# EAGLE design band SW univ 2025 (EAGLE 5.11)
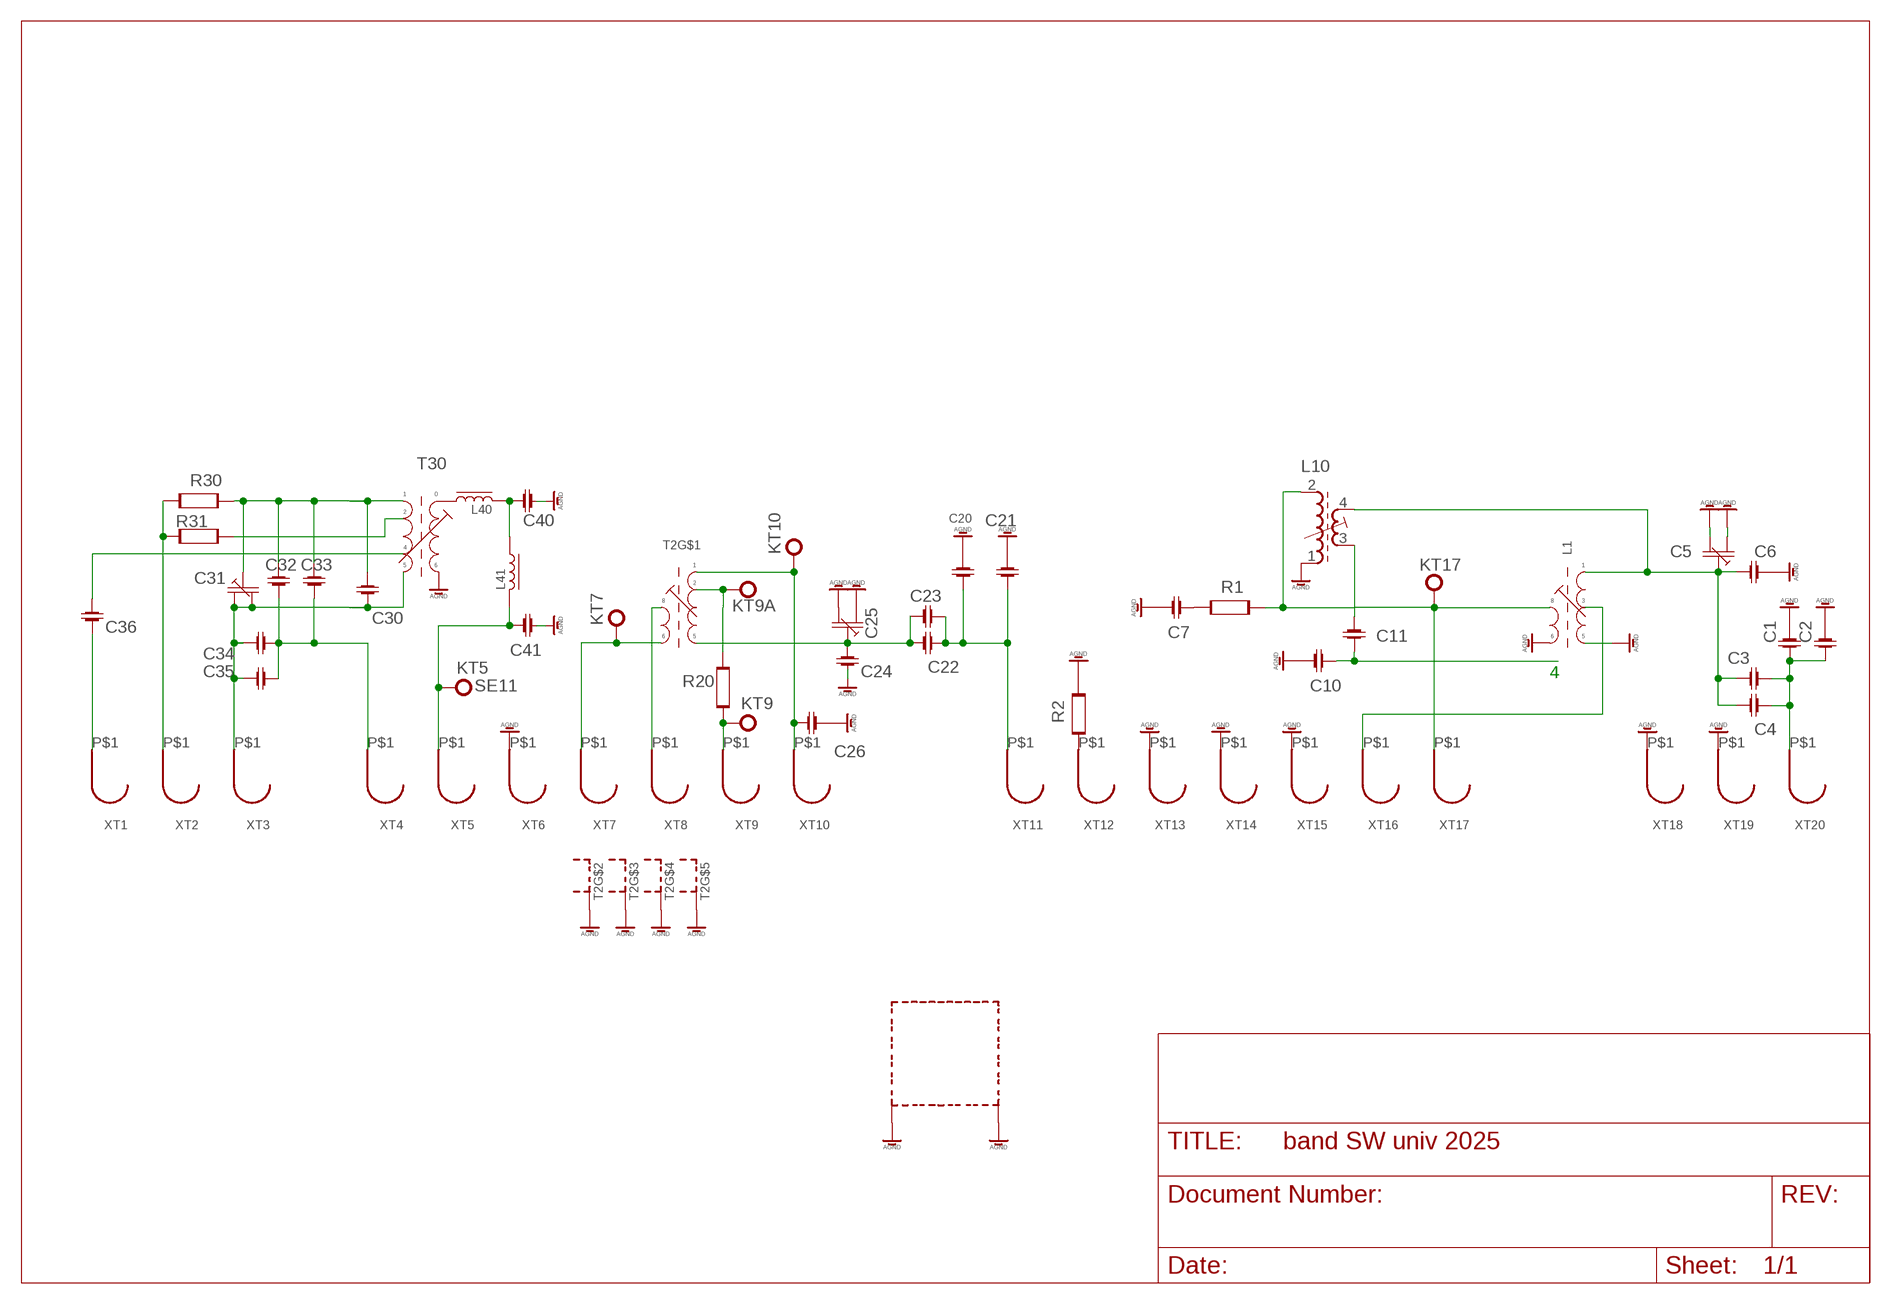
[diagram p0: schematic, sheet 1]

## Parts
C1  C-1206-0805  [RC-SMD-UNIV]
C2  C-1206-0805  [RC-SMD-UNIV]
C3  C-1206-0805  [RC-SMD-UNIV]
C4  C-1206-0805  [RC-SMD-UNIV]
C5  C-TRIM-AM  [C-TRIM-ORIG]
C6  C-1206-0805  [RC-SMD-UNIV]
C7  C-1206-0805  [RC-SMD-UNIV]
C10  C-1206-0805  [RC-SMD-UNIV]
C11  C-1206-0805  [RC-SMD-UNIV]
C20  C-1206-0805  [RC-SMD-UNIV]
C21  C-1206-0805  [RC-SMD-UNIV]
C22  C-1206-0805  [RC-SMD-UNIV]
C23  C-1206-0805  [RC-SMD-UNIV]
C24  C-1206-0805  [RC-SMD-UNIV]
C25  C-TRIM-AM  [C-TRIM-ORIG]
C26  C-1206-0805  [RC-SMD-UNIV]
C30  C-1206-0805  [RC-SMD-UNIV]
C31  C-TRIM-AM  [C-TRIM-ORIG]
C32  C-1206-0805  [RC-SMD-UNIV]
C33  C-1206-0805  [RC-SMD-UNIV]
C34  C-1206-0805  [RC-SMD-UNIV]
C35  C-1206-0805  [RC-SMD-UNIV]
C36  C-1206-0805  [RC-SMD-UNIV]
C40  C-1206-0805  [RC-SMD-UNIV]
C41  C-1206-0805  [RC-SMD-UNIV]
KT5  SE11  [SE11]
KT7  SE11  [SE11]
KT9  SE11  [SE11]
KT9A  SE11  [SE11]
KT10  SE11  [SE11]
KT17  SE11  [SE11]
L1  L-MOD-SW-IN-OPEN  [L-KW-LARGE]
L10  71-4-2143  [71-5]
L40  L-US0207/10  [0207/10]
L41  L-US0207/10  [0207/10]
R1  R-1206-0805  [RC-SMD-UNIV]
R2  R-1206-0805  [RC-SMD-UNIV]
R20  R-1206-0805  [RC-SMD-UNIV]
R30  R-1206-0805  [RC-SMD-UNIV]
R31  R-1206-0805  [RC-SMD-UNIV]
T2  L-MOD-SW-MIX-SHIELD  [L-10-7-MM]
T30  L-MOD-OSC-SW  [L-KW-LARGE]
XT1  CONTACT-RF  [CONTACT-RF]
XT2  CONTACT-RF  [CONTACT-RF]
XT3  CONTACT-RF  [CONTACT-RF]
XT4  CONTACT-RF  [CONTACT-RF]
XT5  CONTACT-RF  [CONTACT-RF]
XT6  CONTACT-RF  [CONTACT-RF]
XT7  CONTACT-RF  [CONTACT-RF]
XT8  CONTACT-RF  [CONTACT-RF]
XT9  CONTACT-RF  [CONTACT-RF]
XT10  CONTACT-RF  [CONTACT-RF]
XT11  CONTACT-RF  [CONTACT-RF]
XT12  CONTACT-RF  [CONTACT-RF]
XT13  CONTACT-RF  [CONTACT-RF]
XT14  CONTACT-RF  [CONTACT-RF]
XT15  CONTACT-RF  [CONTACT-RF]
XT16  CONTACT-RF  [CONTACT-RF]
XT17  CONTACT-RF  [CONTACT-RF]
XT18  CONTACT-RF  [CONTACT-RF]
XT19  CONTACT-RF  [CONTACT-RF]
XT20  CONTACT-RF  [CONTACT-RF]

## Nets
AGND: C1.P$2 C2.P$2 C5.P$6 C5.P$7 C6.P$2 C7.P$1 C10.P$1 C20.P$2 C21.P$2 C24.P$1 C25.P$6 C25.P$7 C26.P$1 C40.P$1 C41.P$2 L1.P$1 L1.P$2 L10.1(E1) L10.S1 L10.S2 R2.P$2 T2.11(S) T2.12(S) T2.13(S) T2.14(S) T30.P$2 XT6.P$1 XT13.P$1 XT14.P$1 XT15.P$1 XT18.P$1 XT19.P$1
KT17: KT17.MP L1.P$6 L10.2(A1) R1.P$2 XT17.P$1
N$1: C1.P$1 C2.P$1 C3.P$2 C4.P$2 XT20.P$1
N$2: C3.P$1 C4.P$1 C5.P$5 C6.P$1 L1.P$3 L10.4(A2)
N$3: KT7.MP T2.4 XT7.P$1
N$4: C7.P$2 R1.P$1
N$5: T2.5 XT8.P$1
N$6: KT9.MP R20.P$1 XT9.P$1
N$7: R30.P$2 R31.P$1 XT2.P$1
N$8: L1.P$5 XT16.P$1
N$9: C26.P$2 KT10.MP T2.1 XT10.P$1
N$10: R2.P$1 XT12.P$1
N$11: R31.P$2 T30.P$1
N$12: C22.P$2 C23.P$2 C24.P$2 C25.P$5 T2.3
N$13: C20.P$1 C21.P$1 C22.P$1 C23.P$1 XT11.P$1
N$14: C11.P$2 L10.3(E2)
N$15: C10.P$2 C11.P$1
N$18: L40.1 T30.P$3
N$19: C30.P$1 C31.P$5 C32.P$1 C33.P$1 R30.P$1 T30.P$5
N$20: C30.P$2 C31.P$6 C31.P$7 C34.P$2 C35.P$2 T30.P$6 XT3.P$1
N$21: C32.P$2 C33.P$2 C34.P$1 C35.P$1 XT4.P$1
N$23: C41.P$1 KT5.MP L41.2 XT5.P$1
N$24: C36.P$1 T30.P$4
N$25: C40.P$2 L40.2 L41.1
N$26: C36.P$2 XT1.P$1
N$31: KT9A.MP R20.P$2 T2.2

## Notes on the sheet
- 4

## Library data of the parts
C1-C4 C6 C7 C10 C11 C20-C24 C26 C30 C32-C36 C40 C41 = OKEAH:C-1206-0805
C5 C25 C31 = OKEAH:C-TRIM-AM
KT5 KT7 KT9 KT9A KT10 KT17 = solpad:SE11: SOLDER PAD
L1 = OKEAH:L-MOD-SW-IN-OPEN
L10 = L NEOSID:71-4-: TRANSFORMER adjustable filter transformer; OC_FARNELL: unknown; OC_NEWARK: unknown
L40 L41 = rcl:L-US: INDUCTOR, American symbol
R1 R2 R20 R30 R31 = OKEAH:R-1206-0805
T2 = OKEAH:L-MOD-SW-MIX-SHIELD
T30 = OKEAH:L-MOD-OSC-SW
XT1-XT20 = OKEAH:CONTACT-RF

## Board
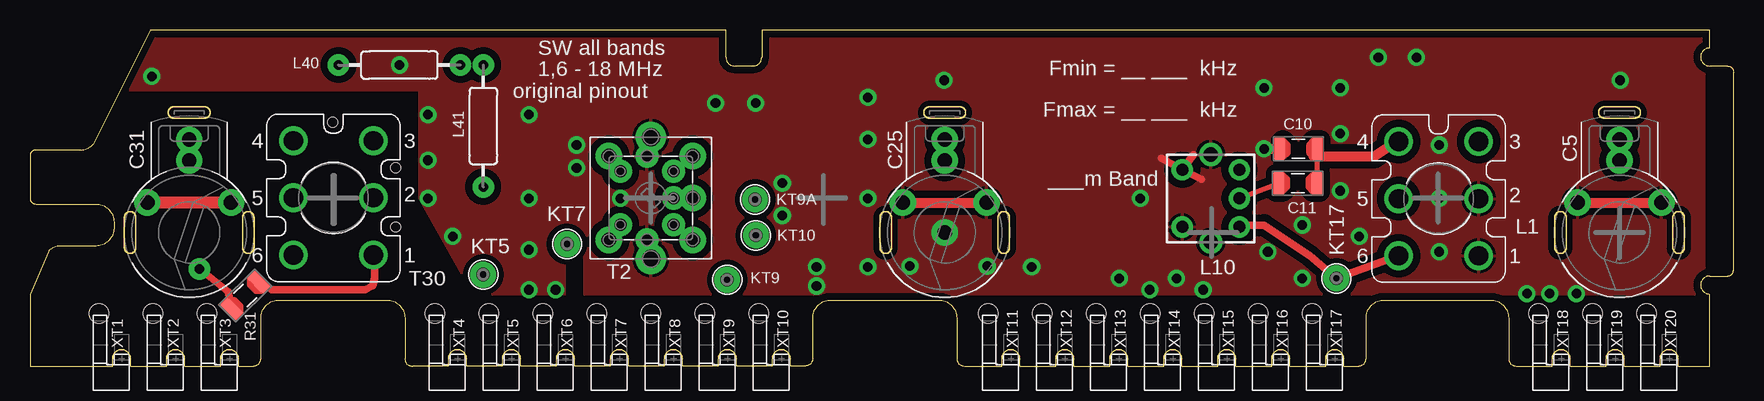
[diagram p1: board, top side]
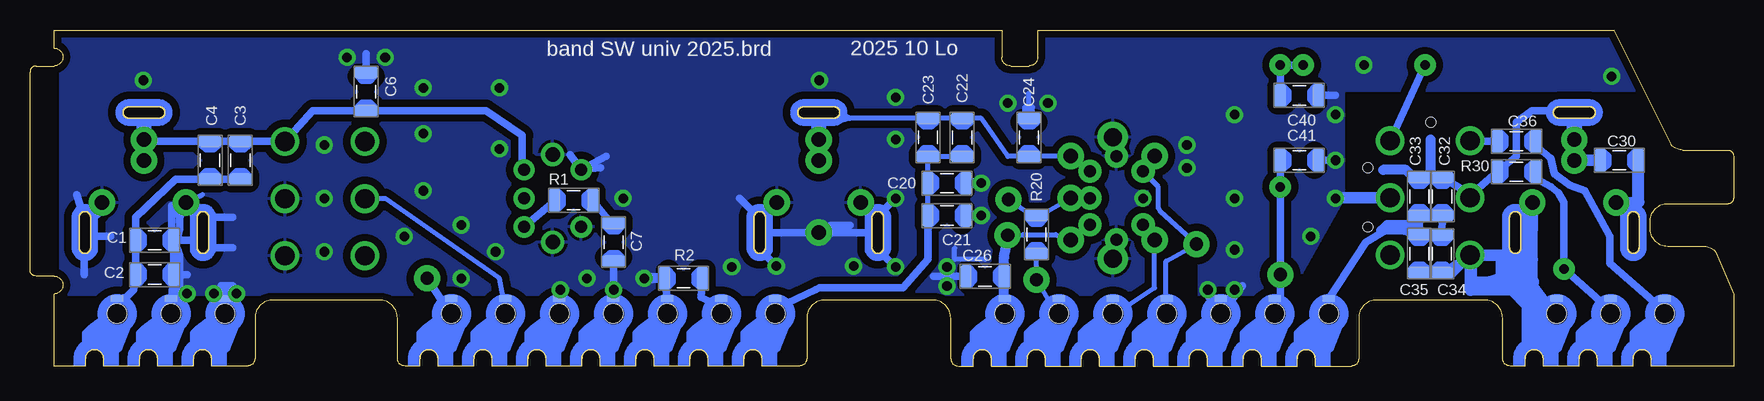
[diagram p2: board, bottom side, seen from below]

Size 142 x 28 mm. Coordinates in mm from the lower left corner, seen from the top.
Outline: 139 segments
Copper layers (1*16): Top 0.035mm / dielectric 1.5mm / Bottom 0.035mm
Design rules "default *": minimum track width 10mil, minimum drill 24mil, track to track 8mil, track to pad 8mil, pad to pad 8mil, via to via 8mil, smd to smd 8mil, copper to edge 8mil, drill to drill 8mil, minimum pad ring 10mil, minimum via ring 8mil, stop-mask expansion 4mil, vias tented up to drill 0mil, thermal gap 10mil
Holes 0.8 mm at 30.48,16.51 30.48,11.59 25.24,20.32
tRestrict: 1 lines
bRestrict: 2 lines

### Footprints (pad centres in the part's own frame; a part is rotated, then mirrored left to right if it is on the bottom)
RC-SMD-UNIV = smd 0.965 x 1.93: P$1 -1.587,0; P$2 1.587,0
C-TRIM-ORIG = drill 1.2 pad 2.184 round: P$4 7.739,0; P$5 5.992,0; P$6 2.5,3.493; P$7 2.5,-3.493
SE11 = drill 1.1 pad 2.159 round: MP 0,0
L-KW-LARGE = drill 1.6 round: P$1 0,0; P$2 0,4.763; P$3 0,9.525; P$4 -6.668,9.525; P$5 -6.668,4.763; P$6 -6.668,0
71-5 = drill 1 pad 1.778 round: 1 2.381,-2.381; 2 2.381,2.381; 3 0,2.381; 4 -2.381,2.381; 5 -2.381,-2.381 | drill 1.2 pad 1.93 round: S1 -3.651,0; S2 3.651,0
0207/10 = drill 0.8 pad 1.778 round: 1 -5.08,0; 2 5.08,0
L-10-7-MM = drill 1 pad 1.93 round: 1 -2.223,-1.905; 2 0,-1.905; 3 2.223,-1.905; 4 2.223,2.54; 5 -2.223,2.54; 12 -3.493,0.318; 13 3.493,0.318 | drill 1.2 pad 2.184 round: 6 -3.493,-3.493; 7 0,-3.493; 8 3.493,-3.493; 9 3.493,3.493; 10 -3.493,3.493 | drill 1.5 pad 2.54 round: 11 -5.08,0; 14 5.08,0
CONTACT-RF = smd 1.016 x 0.508 bottom: P$1 1,-5.625 | hole 1.6: 1,-4.375

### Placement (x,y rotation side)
C1  131.6,10.48 0 bottom
C2  131.6,7.62 0 bottom
C3  124.46,17.15 270 bottom
C4  127,17.15 270 bottom
C5  132.5,11.13 90 top
C6  113.98,22.86 90 bottom
C7  93.34,10.32 90 bottom
C10  105.73,18.1 0 top
C11  105.68,15.24 180 top
C20  65.56,15.24 0 bottom
C21  65.56,12.54 0 bottom
C22  64.29,19.05 90 bottom
C23  67.15,19.05 90 bottom
C24  58.74,19.05 270 bottom
C25  76.25,11.13 90 top
C26  62.39,7.46 0 bottom
C30  9.53,17.15 0 bottom
C31  13.27,11.13 90 top
C32  24.29,14.13 270 bottom
C33  26.19,14.13 270 bottom
C34  24.32,9.36 270 bottom
C35  26.19,9.37 270 bottom
C36  18.1,18.73 0 bottom
C40  36.2,22.54 180 bottom
C41  36.2,17.15 0 bottom
KT5  37.78,7.62 0 top
KT7  44.77,10.16 0 top
KT9  58.12,7.19 0 top
KT9A  60.44,13.88 0 top
KT10  60.51,10.89 0 top
KT17  108.9,7.3 0 top
L1  120.75,9.19 0 top
L10  98.42,13.97 270 top
L40  30.8,25.08 0 top
L41  37.78,20 270 top
R1  96.68,13.81 180 bottom
R2  87.52,7.3 180 bottom
R20  58.1,10.96 90 bottom
R30  18.1,16.19 0 bottom
R31  17.94,5.88 45 top
T2  51.75,14 90 top
T30  28.62,9.25 0 top
XT1  6.75,0 180 top
XT2  11.25,0 180 top
XT3  15.75,0 180 top
XT4  34.75,0 180 top
XT5  39.25,0 180 top
XT6  43.75,0 180 top
XT7  48.25,0 180 top
XT8  52.75,0 180 top
XT9  57.25,0 180 top
XT10  61.75,0 180 top
XT11  80.88,0 180 top
XT12  85.38,0 180 top
XT13  89.88,0 180 top
XT14  94.38,0 180 top
XT15  98.88,0 180 top
XT16  103.38,0 180 top
XT17  107.88,0 180 top
XT18  126.75,0 180 top
XT19  131.25,0 180 top
XT20  135.75,0 180 top

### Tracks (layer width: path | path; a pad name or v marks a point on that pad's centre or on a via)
AGND  (via drill 0.8 pad 1.42, 1.2 pad 2.18)
  Top 0.61: C5.P$6 C5.P$7 | 96.04,16.35 94.3,17.31 | 96.04,16.35 97.63,15.56 | 96.04,16.35 97,17.62
  Top 0.813: 102.55,18.1 C10.P$1
  Bottom 0.406: 127.64,14.29 128.27,13.97 C5.P$6 | 129.54,12.07 128.91,13.65 | C24.P$1 | C24.P$1 58.42,20.8 58.42,21.59 59.05,21.59 59.05,20.8 C24.P$1 | C24.P$1 58.74,22.7 | 62.39,8.89 64.93,8.89 64.93,9.84
  Bottom 0.61: XT19.P$1 130.18,5.72 C2.P$2 | C2.P$2 C1.P$2 128.59,10.48 | 137.48,7.62 137.48,8.89 | 136.53,10.8 135.25,10.8 | 138.11,14.29 137.79,13.34 | C2.P$2 129.54,7.62 | 129.54,7.62 128.91,7.62 | 128.59,6.35 129.54,5.4 | 126.68,12.39 125.09,12.39 | 126.68,9.84 125.09,9.84 | 130.18,12.39 130.18,11.12 | 72.27,11.12 76.27,11.12 | 76.27,11.12 76.33,11.12 | 75.25,11.75 73.66,11.75 | 44.13,6.35 43.5,5.4 XT6.P$1 41.91,5.4 40.96,6.67 | C41.P$2 33.34,17.15 | C40.P$1 33.18,22.55 | XT18.P$1 125.09,6.67 126.05,6.67 125.73,6.03 v124.78,6.03 | 88.9,5.72 R2.P$2 | 81.92,13.02 82.87,13.97 | 79.69,8.26 80.64,9.21 | v69.85,13.97 70.8,13.02 | v69.85,8.26 70.8,9.21 | 76.27,11.12 80.33,11.12 | C6.P$2 113.98,26.04 | C2.P$2 129.54,7.62 | 129.54,7.62 129.54,8.89 129.86,8.89 129.86,5.72 129.54,5.72 129.54,7.31 129.54,9.21 129.86,10.16 129.54,11.43 129.54,13.65 130.18,12.39 | 130.18,12.39 130.18,13.34 | v93.34,6.35 C7.P$1 | 96.04,16.35 94.46,16.51 | 96.04,16.35 93.98,17.46 | 96.04,16.35 97,17.62 | C26.P$1 66.67,7.46
  Bottom 0.813: R2.P$2 90.17,7.31 | XT13.P$1 88.9,5.72 | XT14.P$1 93.34,5.72 v93.34,6.35 | XT15.P$1 97.79,5.72 v97.79,6.35 | v62.71,15.24 C20.P$2 | v62.71,12.54 C21.P$2
  Bottom 1.016: T30.P$2 v33.18,13.97
  other vias: 33.18,17.15 33.18,20.96 30.8,25.08 41.59,6.35 43.81,6.35 65.56,6.67 69.85,22.39 106.05,7.3 110.81,10.8 103.19,9.53 10.16,24.13 126.68,6.03 117.47,18.42 95.57,7.3 65.56,8.26 57.15,21.91 92.55,13.97 90.81,7.3 76.25,11.13 79.79,8.33 73.34,8.33 109.22,19.37 117.47,9.53 109.22,14.61 35.24,10.8 106.05,11.75 112.39,25.72 115.57,25.72 128.91,6.03 117.47,13.97 102.87,18.1 41.59,9.69 41.59,13.97 45.56,18.42 41.59,20.96 76.2,23.81 69.85,18.89 132.56,23.81 109.22,23.18 102.87,23.18 83.5,8.26 60.48,21.91 49.21,13.97 45.56,16.51
  pour Top (isolate 0.61): 37,6 32.5,14 32.5,23 7.5,23 10,28 58,28 58,25 61,25 61,28 139.5,28 139.5,6
  pour Bottom (isolate 0.61): 10,28 139.5,28 139.5,6 37,6 32.5,14 32.5,23 7.5,23
KT17
  Top 0.61: L10.2 101.28,11.75 102.87,11.75 106.68,9.21 KT17.MP L1.P$6
  Bottom 0.61: XT17.P$1 107.63,5.4 KT17.MP | L10.2 98.74,13.34 98.11,13.34 R1.P$2
N$1
  Bottom 0.61: XT20.P$1 133.99,5.72 133.35,6.35 C2.P$1 C1.P$1 133.19,12.39 129.86,15.56 C4.P$2 C3.P$2
N$2
  Bottom 0.61: C5.P$5 132.4,18.74 C4.P$1 C3.P$1 121.92,18.74 L1.P$3 118.43,21.28 C6.P$1 103.98,21.28 100.97,19.21 100.97,16.83 L10.4
N$3
  Bottom 0.406: XT7.P$1 47.31,5.56 47.31,8.73 KT7.MP 47.78,12.86 47.94,13.18 47.94,14.92 T2.4
N$4
  Bottom 0.61: R1.P$1 93.82,12.23 C7.P$2
N$5
  Bottom 0.406: T2.5 48.26,10.48 48.26,6.51 50.64,4.92 XT8.P$1
N$6
  Bottom 0.406: XT9.P$1 56.99,5.24 KT9.MP R20.P$1
N$7  (via drill 0.8 pad 1.78)
  Top 0.61: v14.13,8.1 16.51,6.19 R31.P$1
  Bottom 0.61: R30.P$2 16.35,15.56 15.24,14.92 14.61,14.45 14.13,13.65 v14.13,8.1 11.11,5.4 XT2.P$1
N$8
  Bottom 0.406: XT16.P$1 102.55,5.72 102.87,7.31 112.39,13.97 112.39,13.95 L1.P$5
N$9
  Bottom 0.406: T2.1 55.24,10.48 56.52,10.96 59.21,10.96 60.43,10.85 | 60.8,5.72 61.28,5.72 XT10.P$1
  Bottom 0.813: 60.8,5.72 C26.P$2 60.8,9.05 60.43,10.85 60.33,10.8 KT10.MP
N$10
  Bottom 0.61: XT12.P$1 85.41,5.4 86.04,5.72 R2.P$1
N$11
  Top 0.61: R31.P$2 20.16,6.35 27.94,6.35 28.57,6.67 28.73,7.31 28.73,8.73 T30.P$1
N$12
  Bottom 0.406: T2.3 55.24,17.46 C24.P$2 60.48,17.46 62.71,20.64 C22.P$2 C23.P$2 73.66,20.64 | 73.66,20.64 74.14,20.96 74.45,20.48 73.66,20.64 | 73.66,20.64 74.77,20.32 76.2,20.16 C25.P$5
N$13
  Bottom 0.406: C22.P$1 C23.P$1 C20.P$1 C21.P$1
  Bottom 0.61: XT11.P$1 79.38,5.56 78.9,5.24 76.52,6.35 76.2,6.51 69.22,6.51 67.15,8.89 C21.P$1
N$14
  Top 0.406: L10.3 C11.P$2
N$15
  Top 0.406: C11.P$1 107.31,16.19 C10.P$2
N$16
  Bottom 0.813: 26.35,11.75 28.89,11.75 29.37,11.27
N$17
  Bottom 0.406: 127.95,13.34 128.27,13.65 128.91,13.02 128.27,12.39
N$18
  Bottom 0.61: T30.P$3 L40.1
N$19
  Bottom 0.406: 15.56,21.28 15.24,20.64 14.61,20.32 13.34,20.32 C31.P$5
  Bottom 0.61: 21.91,14.29 C32.P$1 C33.P$1 | 15.56,21.28 16.83,21.28 18.1,20.32 18.1,17.46 R30.P$1 21.91,14.29 | 21.91,14.29 T30.P$5 21.91,14.29
  Bottom 1.016: C30.P$1 C31.P$5
N$20
  Top 1.016: C31.P$7 C31.P$6
  Bottom 0.406: 15.88,4.77 16.51,4.77
  Bottom 0.61: XT3.P$1 15.56,5.4 15.88,4.77 | C35.P$2 C34.P$2 T30.P$6
  Bottom 1.016: C30.P$2 7.94,13.65 C31.P$6 | 16.51,4.77 15.88,5.4 16.83,6.67 16.82,6.98 16.81,8.89 | 16.81,8.89 C31.P$7 | T30.P$6 19.37,9.21 19.05,8.89 16.81,8.89
  Bottom 1.27: 16.82,6.98 19.37,6.99
N$21
  Bottom 0.61: C32.P$2 C34.P$1 C35.P$1 | C35.P$1 C33.P$2 | C35.P$1 27.62,11.27 | 27.62,11.27 | 27.62,11.27 29.05,11.27 30.64,10.32 XT4.P$1
N$22
  Top 0.813: 107,17.46 112.08,17.46 113.98,18.74
N$23
  Bottom 0.61: L41.2 C41.P$1 KT5.MP | KT5.MP 37.78,6.35 37.78,5.72 | 37.78,5.72 XT5.P$1 37.78,5.72 | 37.78,5.72 KT5.MP
N$24
  Bottom 0.61: C36.P$1 20.95,18.74 T30.P$4
N$25
  Bottom 0.61: C40.P$2 L41.1 L40.2
N$26
  Bottom 0.61: XT1.P$1 6.67,5.4 10.32,8.57 10.32,10.8 12.38,14.61 13.65,15.08 14.92,16.04 15.24,17.31 16.19,18.1 C36.P$2
N$27
  Bottom 0.61: 21.91,9.21 23.5,7.62
  Bottom 1.016: 18.41,6.35 21.91,6.35 21.91,9.21 21.91,6.99 20.32,6.99 19.37,7.31 19.37,8.89 18.73,7.94 17.14,7.94 17.14,5.08 | 18.41,6.35 17.14,6.35 16.51,3.81 17.14,2.86 17.14,5.08 | 17.14,5.08 18.41,6.35
N$28
  Bottom 0.406: 136.53,12.39 136.21,12.7 136.84,13.34 137.16,13.02
N$29
  Bottom 0.813: 26.19,15.56 26.51,15.56 27.3,16.35 29.21,16.35
N$30
  Bottom 0.813: 25.24,15.88 25.24,18.89
N$31
  Bottom 0.406: T2.2 55.24,13.97 57.47,12.7 R20.P$2 58.74,12.7 KT9A.MP

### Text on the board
tPlace: SW all bands | Fmin = __ ___ kHz | 1,6 - 18 MHz | original pinout | Fmax = __ ___ kHz | ___m Band
bPlace: 2025 10 Lo | band SW univ 2025.brd
tDocu: ANT Modul | grid placement = 0.125mm | grid placement = 0.125mm | grid SMD = 0.3175mm | grid SMD = 0.3175mm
